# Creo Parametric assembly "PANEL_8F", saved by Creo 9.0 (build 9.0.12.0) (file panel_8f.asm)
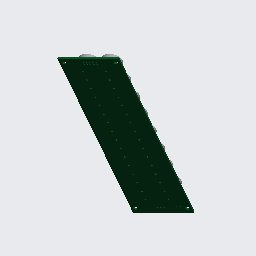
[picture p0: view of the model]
Units: millimeter Newton Second (mmNs); MM, TONNE, SECS

Created from: XX_MMNS_ASM_DESIGN_ABS.ASM

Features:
  1. datum plane "ASM_RIGHT"
  2. datum plane "ASM_TOP"
  3. datum plane "ASM_FRONT"
  4. coordinate system
  5. coordinate system
  6. component "PCB_8F"
  7. coordinate system
  8. component "TX16"
  9. coordinate system
  10. component "TX16"
  11. coordinate system
  12. component "TX16"
  13. coordinate system
  14. component "TX16"
  15. coordinate system
  16. component "TX16"
  17. coordinate system
  18. component "TX16"
  19. coordinate system
  20. component "TX16"
  21. coordinate system
  22. component "TX16"
  23. coordinate system
  24. component "TX16"
  25. coordinate system
  26. component "TX16"
  27. coordinate system
  28. component "TX16"
  29. coordinate system
  30. component "TX16"
  31. coordinate system
  32. component "TX16"
  33. coordinate system
  34. component "TX16"
  35. coordinate system
  36. component "TX16"
  37. coordinate system
  38. component "TX16"

Other named items: ACS0, ACS1, ACS2, ACS3, ACS4, ACS5, ACS6, ACS7, ACS8, ACS9, ACS10, ACS11, ACS12, ACS13, ACS14, ACS15, ACS16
